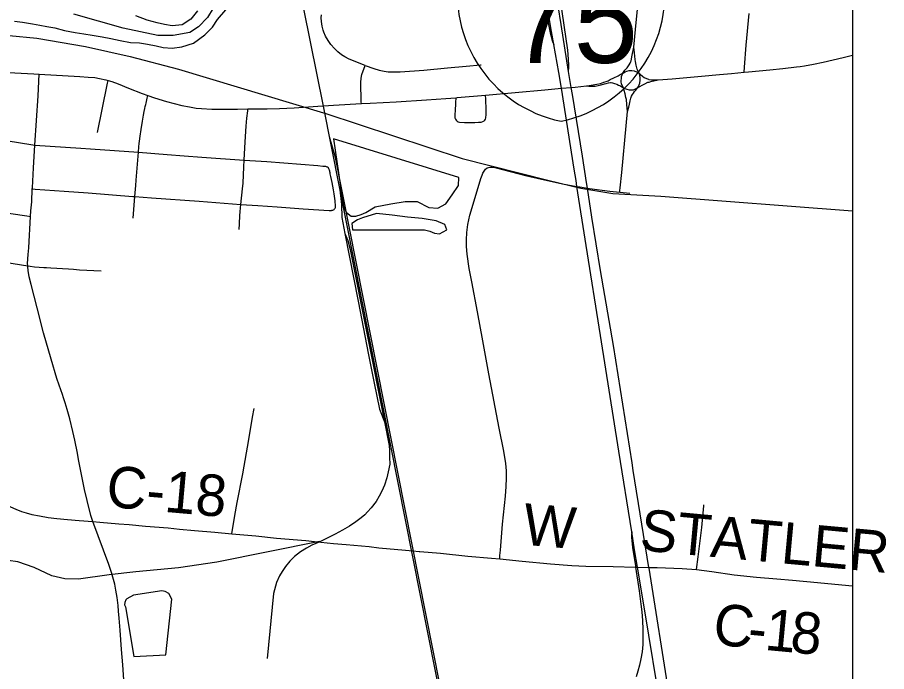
# Model space of a CAD drawing. Extents: x -87 to 2145, y -2128 to 440.
# Drawn here: x 199.98 to 231.41, y -1162.55 to -1138.91 of the extents above; entities that cross this region are included whole.
import ezdxf

# ---------------------------------------------------------------- set-up
doc = ezdxf.new("R2010")
doc.units = 0
for name, color, linetype in [('GM_X_City_Street', 7, 'Continuous'), ('GM_X_County_Road', 7, 'Continuous'), ('GM_X_County_Road_Text', 7, 'Continuous'), ('GM_X_Interchange_Ramps', 7, 'Continuous'), ('GM_X_Interstate_Location', 7, 'Continuous'), ('GM_X_Interstate_Route', 7, 'Continuous'), ('GM_X_Interstate_Shield', 7, 'Continuous'), ('GM_X_Major_River', 7, 'Continuous'), ('GM_X_Minor_Lake', 7, 'Continuous'), ('GM_X_Rail_Line', 7, 'Continuous'), ('GM_X_Township', 7, 'Continuous'), ('GM_X_Township_Road', 7, 'Continuous'), ('GM_X_Township_Text', 7, 'Continuous'), ('SC_Scratch1', 7, 'Continuous')]:
    doc.layers.add(name, color=color, linetype=linetype)

msp = doc.modelspace()

# ---------------------------------------------------------------- linework, layer by layer
at = {"layer": 'GM_X_City_Street'}
msp.add_line((222.497, -1141.064), (222.493, -1141.04), dxfattribs=at)
for points in [[(222.274, -1139.98), (222.338, -1139.338), (222.555, -1137.151), (222.646, -1136.304), (222.735, -1135.339), (222.807, -1134.506), (222.893, -1133.51), (222.895, -1133.476), (223.036, -1132.193)], [(212.421, -1142.023), (212.419, -1141.97), (212.409, -1141.724), (212.399, -1141.474), (212.396, -1141.264), (212.411, -1141.106), (212.442, -1140.968), (212.559, -1140.645), (211.983, -1140.412), (211.823, -1140.334), (211.701, -1140.256), (211.574, -1140.156), (211.445, -1140.033), (211.317, -1139.887), (211.214, -1139.742), (211.127, -1139.587), (211.065, -1139.438), (211.042, -1139.368), (211.007, -1139.227), (210.979, -1139.055), (210.972, -1138.924), (210.975, -1138.809)], [(226.258, -1140.889), (226.273, -1140.707), (226.338, -1139.907), (226.443, -1138.765)], [(222.171, -1140.473), (222.213, -1140.276), (222.274, -1139.98)], [(222.336, -1140.501), (222.323, -1140.422), (222.299, -1140.187), (222.274, -1139.98)], [(221.829, -1141.043), (221.845, -1140.988), (221.875, -1140.922), (221.95, -1140.818), (222.026, -1140.727), (222.106, -1140.623), (222.144, -1140.561), (222.165, -1140.502), (222.171, -1140.473)], [(222.405, -1140.799), (222.396, -1140.776), (222.357, -1140.633), (222.336, -1140.501)], [(212.559, -1140.645), (212.869, -1140.75), (213.067, -1140.813), (213.241, -1140.852), (213.385, -1140.871), (213.546, -1140.878), (213.823, -1140.869), (214.674, -1140.808), (215.54, -1140.732), (216.211, -1140.673), (216.733, -1140.626), (216.75, -1140.625)], [(222.493, -1141.04), (222.484, -1140.992), (222.451, -1140.915), (222.405, -1140.799)], [(202.878, -1143.063), (203.05, -1142.235), (203.246, -1141.28), (203.265, -1141.188)], [(221.825, -1141.307), (221.811, -1141.231), (221.821, -1141.071), (221.829, -1141.043)], [(222.484, -1141.285), (222.492, -1141.257), (222.502, -1141.195), (222.505, -1141.117), (222.497, -1141.064)], [(221.985, -1141.8), (221.957, -1141.672), (221.925, -1141.543), (221.896, -1141.446), (221.852, -1141.373), (221.825, -1141.307)], [(222.3, -1141.589), (222.345, -1141.536), (222.406, -1141.454), (222.44, -1141.403), (222.468, -1141.34), (222.484, -1141.285)], [(204.166, -1146.163), (204.233, -1145.381), (204.26, -1144.977), (204.274, -1144.791), (204.359, -1143.776), (204.375, -1143.59), (204.389, -1143.463), (204.399, -1143.382), (204.424, -1143.202), (204.461, -1142.955), (204.508, -1142.66), (204.547, -1142.434), (204.569, -1142.312), (204.591, -1142.203), (204.606, -1142.132), (204.624, -1142.049), (204.633, -1142.012), (204.65, -1141.941), (204.68, -1141.821), (204.704, -1141.726)], [(215.836, -1141.809), (215.827, -1141.976), (215.809, -1142.309), (215.804, -1142.374), (215.8, -1142.472), (215.805, -1142.531), (215.821, -1142.584), (215.847, -1142.625), (215.882, -1142.658), (215.926, -1142.681), (215.973, -1142.694), (216.153, -1142.709), (216.521, -1142.703), (216.658, -1142.698), (216.757, -1142.688), (216.808, -1142.674), (216.838, -1142.661), (216.865, -1142.643), (216.887, -1142.618), (216.903, -1142.589), (216.916, -1142.542), (216.927, -1142.41), (216.93, -1142.247), (216.918, -1141.856), (216.914, -1141.713)], [(222.045, -1142.303), (222.022, -1142.05), (222.002, -1141.877), (221.985, -1141.8)], [(222.045, -1142.303), (222.088, -1142.148), (222.114, -1142.046), (222.143, -1141.916), (222.166, -1141.827)], [(222.166, -1141.827), (222.192, -1141.755), (222.224, -1141.697), (222.264, -1141.641), (222.3, -1141.589)], [(208, -1146.576), (208.008, -1146.361), (208.027, -1146.062), (208.037, -1145.937), (208.05, -1145.791), (208.064, -1145.663), (208.123, -1145.105), (208.142, -1144.897), (208.176, -1144.301), (208.186, -1144.061), (208.22, -1143.399), (208.256, -1142.842), (208.283, -1142.554), (208.312, -1142.288), (208.32, -1142.215)], [(221.761, -1145.219), (221.767, -1145.161), (221.776, -1145.068), (221.833, -1144.508), (221.998, -1142.83), (222.045, -1142.303)], [(198.303, -1143.151), (200.465, -1143.501), (200.617, -1143.525), (202.279, -1143.632), (202.623, -1143.656), (204.359, -1143.776), (205.4, -1143.856), (206.013, -1143.91), (206.652, -1143.953), (208.186, -1144.061), (209.005, -1144.119), (210.848, -1144.264), (211.027, -1144.278), (211.072, -1144.281), (211.095, -1144.284), (211.127, -1144.288), (211.147, -1144.292), (211.175, -1144.301), (211.196, -1144.311), (211.215, -1144.327)], [(211.432, -1145.845), (211.447, -1145.83), (211.458, -1145.815), (211.468, -1145.798), (211.479, -1145.771), (211.483, -1145.748), (211.484, -1145.727), (211.482, -1145.66), (211.478, -1145.609), (211.471, -1145.541), (211.461, -1145.456), (211.435, -1145.281), (211.413, -1145.139), (211.364, -1144.873), (211.319, -1144.657), (211.297, -1144.557), (211.29, -1144.525), (211.282, -1144.49), (211.275, -1144.462), (211.266, -1144.425), (211.258, -1144.398), (211.249, -1144.376), (211.233, -1144.348), (211.215, -1144.327)], [(217.425, -1158.478), (217.433, -1158.356), (217.447, -1158.161), (217.525, -1157.218), (217.627, -1156.207), (217.656, -1155.863), (217.673, -1155.564), (217.664, -1155.288), (217.638, -1155.022), (217.567, -1154.582), (217.403, -1153.748), (217.035, -1151.782), (216.809, -1150.59), (216.616, -1149.542), (216.411, -1148.462), (216.324, -1147.979), (216.244, -1147.462), (216.219, -1147.186), (216.216, -1146.942), (216.231, -1146.682), (216.268, -1146.391), (216.341, -1146.058), (216.421, -1145.778), (216.745, -1144.73), (216.792, -1144.607), (216.817, -1144.538), (216.856, -1144.464), (216.91, -1144.397), (216.967, -1144.344)], [(216.967, -1144.344), (217.06, -1144.322), (217.14, -1144.313), (217.242, -1144.329), (217.576, -1144.415), (218.357, -1144.623), (218.931, -1144.755), (219.698, -1144.917), (220.217, -1145.013), (220.317, -1145.031), (220.592, -1145.077), (220.674, -1145.091), (221.408, -1145.188), (221.761, -1145.219), (222.127, -1145.254)], [(200.522, -1145.102), (200.62, -1145.109), (201.672, -1145.187), (202.536, -1145.249), (204.156, -1145.376), (204.233, -1145.381), (204.835, -1145.426), (206.56, -1145.55), (208.064, -1145.663), (208.671, -1145.708), (209.377, -1145.757), (210.317, -1145.826), (211.25, -1145.882), (211.281, -1145.883), (211.312, -1145.882), (211.34, -1145.879), (211.357, -1145.877), (211.386, -1145.87), (211.417, -1145.856), (211.432, -1145.845)], [(195.696, -1145.341), (195.798, -1145.357), (196.932, -1145.537), (197.748, -1145.668), (197.942, -1145.699), (199.611, -1145.966), (199.746, -1145.988), (200.33, -1146.082), (200.461, -1146.103)], [(195.607, -1147.124), (195.742, -1147.145), (196.777, -1147.304), (197.668, -1147.442), (198.556, -1147.581), (199.534, -1147.748), (200.356, -1147.889), (200.445, -1147.901), (200.599, -1147.918), (200.771, -1147.933), (200.943, -1147.945), (201.03, -1147.949), (201.197, -1147.958), (201.828, -1147.999), (202.007, -1148.01), (202.232, -1148.024), (203.006, -1148.069)], [(207.732, -1157.573), (207.849, -1156.903), (207.931, -1156.435), (208.129, -1155.406), (208.348, -1154.164), (208.487, -1153.359), (208.546, -1153.035)]]:
    msp.add_lwpolyline(points, dxfattribs=at)
at = {"layer": 'GM_X_County_Road'}
msp.add_line((210.852, -1142.119), (211.03, -1142.108), dxfattribs=at)
for points in [[(226.258, -1140.889), (226.42, -1140.875), (227.187, -1140.803), (227.661, -1140.757), (228.149, -1140.696), (228.284, -1140.676), (228.443, -1140.651), (228.764, -1140.591), (229.118, -1140.52), (229.839, -1140.356), (230.183, -1140.275)], [(198.119, -1140.82), (199.187, -1140.874), (200.579, -1140.949), (200.775, -1140.961)], [(221.42, -1141.154), (221.552, -1141.092), (221.705, -1141.015), (221.784, -1140.97), (221.875, -1140.922), (221.901, -1140.905)], [(221.901, -1140.905), (221.955, -1140.873), (222.021, -1140.845), (222.107, -1140.828), (222.194, -1140.828), (222.284, -1140.842), (222.371, -1140.87), (222.451, -1140.915)], [(223.148, -1141.162), (223.66, -1141.122), (224.183, -1141.078), (224.722, -1141.028), (225.375, -1140.968), (225.799, -1140.929), (226.258, -1140.889)], [(200.617, -1143.525), (200.731, -1141.741), (200.775, -1140.961)], [(200.775, -1140.961), (202.245, -1141.047), (202.537, -1141.065), (202.78, -1141.084), (202.955, -1141.114), (203.177, -1141.164), (203.265, -1141.188)], [(203.265, -1141.188), (203.397, -1141.226), (203.626, -1141.31), (204.004, -1141.468), (204.496, -1141.653), (204.704, -1141.726)], [(220.575, -1141.383), (220.729, -1141.352), (220.93, -1141.321), (221.073, -1141.29), (221.184, -1141.252), (221.267, -1141.224), (221.34, -1141.193), (221.42, -1141.154)], [(222.451, -1140.915), (222.51, -1140.97), (222.58, -1141.026), (222.646, -1141.074), (222.729, -1141.12), (222.797, -1141.14)], [(222.797, -1141.14), (222.819, -1141.147), (222.903, -1141.158), (223.148, -1141.162)], [(222.824, -1141.242), (222.888, -1141.225), (223, -1141.199), (223.148, -1141.162)], [(215.836, -1141.809), (215.884, -1141.805), (216.914, -1141.713), (219.053, -1141.522), (219.652, -1141.469), (220.008, -1141.438), (220.148, -1141.426), (220.556, -1141.384), (220.575, -1141.383)], [(220.575, -1141.383), (220.651, -1141.394), (220.755, -1141.394), (220.877, -1141.389), (220.981, -1141.373), (221.091, -1141.345), (221.208, -1141.313), (221.273, -1141.29), (221.351, -1141.272), (221.432, -1141.261), (221.456, -1141.265)], [(221.456, -1141.265), (221.505, -1141.272), (221.573, -1141.293), (221.659, -1141.324), (221.721, -1141.35), (221.786, -1141.381), (221.841, -1141.412), (221.896, -1141.446)], [(221.896, -1141.446), (221.948, -1141.48), (222.021, -1141.506), (222.106, -1141.519), (222.164, -1141.522), (222.255, -1141.519), (222.338, -1141.493), (222.406, -1141.454)], [(222.406, -1141.454), (222.492, -1141.407), (222.578, -1141.352), (222.666, -1141.303), (222.781, -1141.253), (222.824, -1141.242)], [(204.704, -1141.726), (204.946, -1141.81), (205.369, -1141.94), (205.654, -1142.023), (205.925, -1142.089), (206.2, -1142.144), (206.444, -1142.182), (206.641, -1142.204), (207.018, -1142.222), (207.938, -1142.22), (208.32, -1142.215)], [(212.421, -1142.023), (212.741, -1142.005), (213.674, -1141.957), (214.771, -1141.888), (215.475, -1141.837), (215.836, -1141.809)], [(208.32, -1142.215), (209.02, -1142.205), (209.463, -1142.194), (209.987, -1142.17), (210.852, -1142.119)], [(211.03, -1142.108), (211.056, -1142.106), (211.414, -1142.079), (212.421, -1142.023)], [(200.522, -1145.102), (200.523, -1145.062), (200.565, -1144.343), (200.617, -1143.525)], [(200.461, -1146.103), (200.474, -1145.895), (200.5, -1145.568), (200.522, -1145.102)], [(200.356, -1147.889), (200.354, -1147.797), (200.373, -1147.479), (200.391, -1147.235), (200.461, -1146.103)], [(201.651, -1152.659), (201.61, -1152.537), (201.496, -1152.203), (201.403, -1151.952), (201.2, -1151.256), (200.924, -1150.304), (200.699, -1149.402), (200.48, -1148.562), (200.412, -1148.278), (200.371, -1148.054), (200.357, -1147.926), (200.356, -1147.889)], [(202.706, -1157.125), (202.638, -1156.904), (202.504, -1156.369), (202.411, -1155.963), (202.238, -1155.12), (202.191, -1154.88), (202.153, -1154.656), (202.056, -1154.183), (201.985, -1153.877), (201.877, -1153.414), (201.788, -1153.081), (201.71, -1152.83), (201.651, -1152.659)], [(199.079, -1156.215), (199.21, -1156.304), (199.338, -1156.386), (199.529, -1156.497), (199.728, -1156.592), (199.927, -1156.68), (200.13, -1156.761), (200.296, -1156.816), (200.507, -1156.867), (200.779, -1156.922), (201.094, -1156.974), (201.409, -1157.013), (201.794, -1157.055), (202.219, -1157.088), (202.706, -1157.125)], [(203.46, -1159.222), (203.384, -1158.964), (203.292, -1158.682), (202.706, -1157.125)], [(202.706, -1157.125), (202.969, -1157.144), (203.654, -1157.203), (204.03, -1157.235), (204.618, -1157.288), (205.434, -1157.358), (205.842, -1157.397), (206.382, -1157.445), (207.116, -1157.512), (207.732, -1157.573)], [(207.732, -1157.573), (208.603, -1157.647), (209.353, -1157.721), (210.415, -1157.814), (210.724, -1157.845), (211.409, -1157.915), (211.867, -1157.955), (212.699, -1158.031), (213.057, -1158.071), (214.015, -1158.154)], [(214.015, -1158.154), (214.285, -1158.185), (214.505, -1158.209)], [(214.505, -1158.209), (214.53, -1158.212), (215.28, -1158.272), (216.276, -1158.371), (217.126, -1158.449), (217.425, -1158.478)], [(217.425, -1158.478), (218.236, -1158.555), (219.264, -1158.653), (220.033, -1158.712), (220.541, -1158.734), (221.525, -1158.754), (222.336, -1158.774), (222.41, -1158.776), (222.818, -1158.785)], [(222.818, -1158.785), (222.908, -1158.787), (223.116, -1158.79), (224.016, -1158.817), (224.537, -1158.86)], [(224.537, -1158.86), (225.094, -1158.935), (225.906, -1159.046), (226.706, -1159.133), (227.441, -1159.196), (228.012, -1159.25), (228.91, -1159.331), (229.792, -1159.414), (230.183, -1159.451)], [(203.965, -1164.472), (203.957, -1164.333), (203.887, -1163.466), (203.835, -1162.845), (203.793, -1162.306), (203.753, -1161.75), (203.695, -1161.047), (203.659, -1160.623), (203.638, -1160.361), (203.622, -1160.165), (203.588, -1159.871), (203.548, -1159.611), (203.501, -1159.385), (203.46, -1159.222)]]:
    msp.add_lwpolyline(points, dxfattribs=at)
at = {"layer": 'GM_X_Interchange_Ramps'}
for points in [[(216.471, -1132.02), (216.549, -1132.167), (217.253, -1133.081), (217.614, -1133.568), (217.794, -1133.823), (217.966, -1134.083), (218.049, -1134.224), (218.173, -1134.455), (218.247, -1134.607), (218.314, -1134.769), (218.431, -1135.127), (218.503, -1135.396), (218.578, -1135.733), (218.734, -1136.551), (219.125, -1138.833), (219.211, -1139.288), (219.244, -1139.461), (219.278, -1139.594), (219.31, -1139.706), (219.333, -1139.78), (219.375, -1139.881)], [(219.915, -1140.858), (219.922, -1140.719), (219.925, -1140.64), (219.915, -1140.421), (219.883, -1140.088), (219.615, -1138.274), (219.553, -1137.786), (219.509, -1137.329), (219.482, -1136.92), (219.467, -1136.543), (219.463, -1136.149), (219.471, -1135.772), (219.495, -1135.396), (219.538, -1135.021), (219.592, -1134.664), (219.664, -1134.277), (219.742, -1133.914)], [(222.197, -1157.493), (222.186, -1157.603), (222.186, -1157.694), (222.228, -1158.06), (222.293, -1158.51), (222.327, -1158.717), (222.336, -1158.774)], [(222.336, -1158.774), (222.461, -1159.625), (222.528, -1160.113), (222.558, -1160.39), (222.582, -1160.701), (222.598, -1161.029), (222.603, -1161.291), (222.596, -1161.57), (222.571, -1161.831), (222.529, -1162.09), (222.48, -1162.315), (222.418, -1162.536), (222.351, -1162.739)]]:
    msp.add_lwpolyline(points, dxfattribs=at)
at = {"layer": 'GM_X_Interstate_Route'}
for points in [[(220.05, -1141.697), (220.008, -1141.438), (219.961, -1141.153), (219.915, -1140.858), (219.649, -1139.16), (219.205, -1136.456), (218.465, -1132.39), (218.434, -1132.233)], [(222.197, -1157.493), (221.728, -1154.582), (221.064, -1150.398), (220.547, -1147.152), (220.217, -1145.013), (220.185, -1144.805), (220.12, -1144.387), (219.652, -1141.469), (219.56, -1140.897), (219.375, -1139.881), (219.29, -1139.416), (218.889, -1137.005)], [(222.207, -1154.999), (221.543, -1150.766), (221.072, -1148.052), (220.753, -1146.127), (220.592, -1145.077), (220.56, -1144.871), (220.413, -1143.922), (220.05, -1141.697)], [(222.823, -1158.811), (222.818, -1158.785), (222.252, -1155.286), (222.207, -1154.999)], [(223.455, -1174.225), (223.499, -1173.888), (223.628, -1172.581), (223.706, -1171.336), (223.74, -1169.958), (223.707, -1168.35), (223.674, -1167.595), (223.636, -1167.022), (223.58, -1166.368), (223.523, -1165.813), (223.451, -1165.226), (223.328, -1164.365), (223.264, -1163.943), (222.666, -1160.351), (222.421, -1158.844), (222.41, -1158.776), (222.302, -1158.15), (222.197, -1157.493)], [(223.564, -1163.462), (222.823, -1158.811)]]:
    msp.add_lwpolyline(points, dxfattribs=at)
at = {"layer": 'GM_X_Interstate_Shield'}
for centre, start, end in [((220.578, -1138.065), 165.8066, 258.463), ((218.703, -1138.065), 281.537, 14.1934)]:
    msp.add_arc(centre, 4.688, start, end, dxfattribs=at)
at = {"layer": 'GM_X_Major_River'}
for points in [[(199.879, -1139.046), (200.17, -1139.079), (200.53, -1139.143), (200.8, -1139.185), (201.051, -1139.238), (201.341, -1139.281), (201.691, -1139.374), (202.072, -1139.448), (202.382, -1139.501), (202.682, -1139.544), (203.043, -1139.608), (203.363, -1139.671), (203.703, -1139.744), (204.074, -1139.808), (204.395, -1139.831), (204.685, -1139.874), (205.005, -1139.937), (205.256, -1139.989), (205.576, -1140.022), (205.928, -1139.965), (206.351, -1139.839), (206.765, -1139.542), (207.039, -1139.254), (207.213, -1138.984), (207.518, -1138.636)], [(206.494, -1138.667), (206.25, -1138.976), (205.937, -1139.173), (205.575, -1139.21), (205.305, -1139.168), (205.035, -1139.105), (204.675, -1139.011), (204.265, -1138.847)]]:
    msp.add_lwpolyline(points, dxfattribs=at)
at = {"layer": 'GM_X_Minor_Lake'}
for points in [[(211.411, -1143.301), (211.77, -1145.755), (211.877, -1145.956), (212.055, -1146.089), (212.215, -1146.091), (212.416, -1146.034)], [(212.416, -1146.034), (212.578, -1145.957), (212.923, -1145.752), (213.486, -1145.64), (213.999, -1145.558), (214.44, -1145.554), (214.857, -1145.771), (215.187, -1145.795), (215.471, -1145.64), (215.707, -1145.323), (215.933, -1144.987), (215.948, -1144.687), (211.411, -1143.301)], [(212.465, -1146.155), (212.283, -1146.222), (212.07, -1146.349), (212.096, -1146.579)], [(212.096, -1146.579), (214.703, -1146.588), (214.892, -1146.631), (215.062, -1146.703), (215.242, -1146.726), (215.373, -1146.658), (215.515, -1146.58), (215.438, -1146.389), (215.119, -1146.254), (214.62, -1146.177), (214.089, -1146.129), (213.539, -1146.051), (212.969, -1145.993), (212.465, -1146.155)], [(205.571, -1159.93), (205.464, -1159.728), (205.325, -1159.656), (205.205, -1159.624), (204.179, -1159.788), (203.936, -1159.924), (203.906, -1159.954), (203.864, -1160.053), (203.853, -1160.133), (203.892, -1160.204), (204.191, -1161.999)], [(204.191, -1161.999), (205.355, -1161.947), (205.571, -1159.93)]]:
    msp.add_lwpolyline(points, dxfattribs=at)
at = {"layer": 'GM_X_Rail_Line'}
msp.add_line((211.052, -1142.352), (211.1, -1142.368), dxfattribs=at)
for points in [[(221.669, -1195.387), (217.209, -1173.171), (211.624, -1145.03), (211.053, -1142.113), (210.114, -1137.448)], [(190.844, -1139.387), (195.951, -1139.301), (198.669, -1139.466), (200.69, -1139.655), (202.443, -1139.957), (204.063, -1140.316), (205.813, -1140.774), (211.052, -1142.352)], [(211.1, -1142.368), (216.068, -1144.004), (219.158, -1144.79), (220.36, -1145.075), (221.516, -1145.271), (223.248, -1145.372), (230.183, -1145.901)], [(225.434, -1214.375), (225.312, -1213.385), (224.249, -1207.809), (221.734, -1195.374), (217.273, -1173.158), (211.484, -1143.974), (211.271, -1143.225)], [(211.624, -1145.03), (211.701, -1145.67), (211.715, -1146.135), (211.823, -1146.716)], [(211.823, -1146.716), (212.309, -1149.166), (212.674, -1151.099), (212.889, -1152.128), (213.071, -1153.059), (213.253, -1153.521)], [(211.823, -1146.716), (211.929, -1146.975), (212.012, -1147.299), (213.253, -1153.521)], [(213.253, -1153.521), (213.425, -1154.383), (213.44, -1154.562), (213.443, -1154.81), (213.446, -1155.05), (213.391, -1155.331), (213.339, -1155.551), (213.26, -1155.817), (213.166, -1156.028), (213.069, -1156.21), (212.953, -1156.404), (212.769, -1156.635), (212.64, -1156.779), (212.547, -1156.881), (212.415, -1156.993), (212.226, -1157.137), (211.991, -1157.292), (211.74, -1157.437), (211.471, -1157.587), (210.917, -1157.856), (210.633, -1157.98), (210.436, -1158.085), (210.218, -1158.216), (210.006, -1158.388), (209.832, -1158.559), (209.676, -1158.745), (209.554, -1158.926), (209.463, -1159.082), (209.347, -1159.334), (209.274, -1159.592), (209.241, -1159.731), (209.019, -1162.077)], [(210.911, -1157.842), (207.193, -1158.588), (205.812, -1158.795), (204.27, -1158.944), (203.304, -1159.052), (202.187, -1159.208), (201.697, -1159.2), (201.227, -1159.093), (200.593, -1158.79), (199.994, -1158.585), (199.293, -1158.48)]]:
    msp.add_lwpolyline(points, dxfattribs=at)
at = {"layer": 'GM_X_Township'}
msp.add_lwpolyline([(207.066, -1138.576), (206.862, -1138.915), (206.537, -1139.253), (206.214, -1139.45), (205.62, -1139.565), (205.059, -1139.56), (203.808, -1139.298), (202.028, -1138.79)], dxfattribs=at)
at = {"layer": 'GM_X_Township_Road'}
msp.add_lwpolyline([(224.537, -1158.86), (224.595, -1158.406), (224.638, -1158.115), (224.734, -1157.336), (224.802, -1156.559), (224.804, -1156.527)], dxfattribs=at)
at = {"layer": 'GM_X_Township_Text'}
msp.add_lwpolyline([(207.066, -1138.576), (206.862, -1138.915), (206.537, -1139.253), (206.214, -1139.45), (205.62, -1139.565), (205.059, -1139.56), (203.808, -1139.298), (202.028, -1138.79)], dxfattribs=at)
at = {"layer": 'SC_Scratch1'}
msp.add_lwpolyline([(-21.617, -825.188), (230.183, -825.188), (230.183, -1245.188), (-21.617, -1245.188)], close=True, dxfattribs=at)

# ---------------------------------------------------------------- texts
at = {"layer": 'GM_X_County_Road_Text'}
for s, rotation, p in [('C-18', 354.9135, (203.156, -1156.584)), ('W', 355.0886, (218.22, -1157.957)), ('STATLER', 354.7377, (222.453, -1158.159)), ('C', 352.599, (225.078, -1161.537)), ('1', 354.6548, (226.972, -1161.761)), ('8', 354.7342, (227.894, -1161.848)), ('-', 354.4773, (226.353, -1161.702))]:
    msp.add_text(s, height=1.5, rotation=rotation, dxfattribs=at).set_placement(p)
at = {"layer": 'GM_X_Interstate_Location'}
for s in ['-', '.', ',']:
    msp.add_text(s, height=0.005, dxfattribs=at).set_placement((219.64, -1138.911))
msp.add_text('75', height=0.005, rotation=0, dxfattribs=at).set_placement((218.618, -1139.945))
at = {"layer": 'GM_X_Interstate_Shield'}
msp.add_text('75', height=3.125, dxfattribs=at).set_placement((217.774, -1140.549))

doc.saveas('drawing.dxf')
